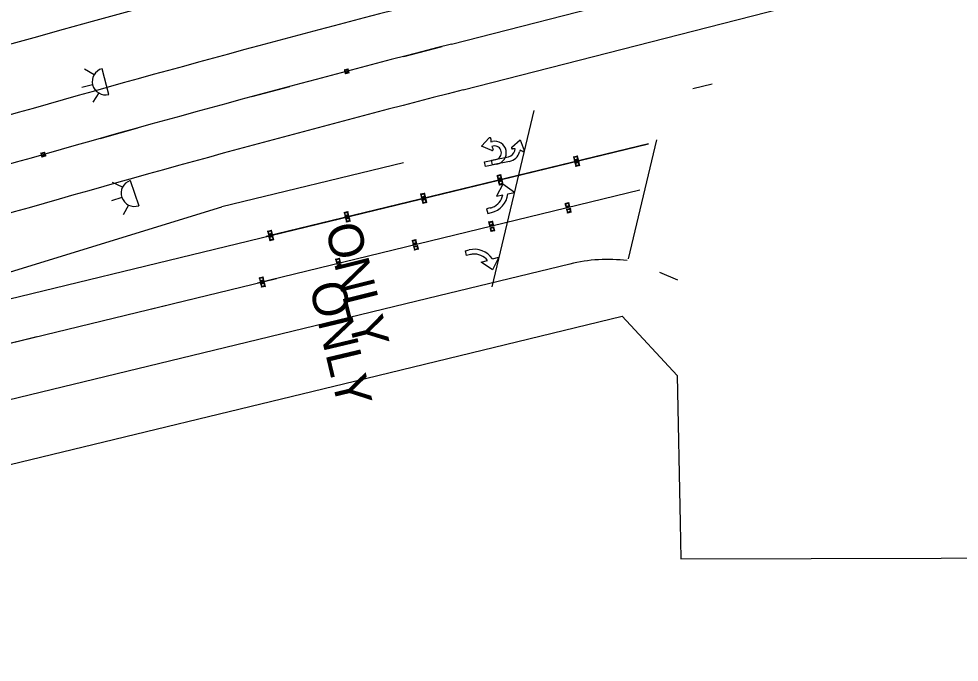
# Model space of a CAD drawing. Extents: x 2471014 to 2497726, y 6959577 to 6980268.
# Drawn here: x 2484090.2 to 2484329.2, y 6967524.6 to 6967688.1 of the extents above; entities that cross this region are included whole.
import ezdxf

# ---------------------------------------------------------------- set-up
doc = ezdxf.new("R2010")
doc.units = 0
for name, color, linetype in [('1', 7, 'Continuous'), ('13', 7, 'Continuous'), ('18', 7, 'Continuous'), ('23', 7, 'Continuous'), ('25', 7, 'Continuous'), ('5', 7, 'Continuous'), ('59', 7, 'Continuous'), ('C-ANNO-NOTE', 7, 'Continuous'), ('Level 30', 7, 'Continuous'), ('p_structure fence', 7, 'Continuous'), ('p_structure wall', 7, 'Continuous'), ('PMK_Del_D-SY_SZ_TYC_CTB', 7, 'Continuous'), ('V7_25', 7, 'Continuous'), ('V7_50', 7, 'Continuous')]:
    doc.layers.add(name, color=color, linetype=linetype)

msp = doc.modelspace()

# ---------------------------------------------------------------- linework, layer by layer
at = {"layer": '1'}
for p, q in [((2484188.08, 6967678.56), (2484197.76, 6967681.06)), ((2484149.41, 6967668.32), (2484159.07, 6967670.92)), ((2484110.85, 6967657.69), (2484120.48, 6967660.38)), ((2484123.99, 6967614.41), (2484133.71, 6967616.76)), ((2484085.12, 6967604.97), (2484094.83, 6967607.33))]:
    msp.add_line(p, q, dxfattribs=at)
at = {"layer": '13'}
for p in [(2484187.94, 6967651.54), (2483808.16, 6967537.76)]:
    msp.add_line(p, (2484141.84, 6967640.35), dxfattribs=at)
msp.add_arc((2485198.7, 6963785.6), 4034, 104.37494, 107.97931, dxfattribs=at)
at = {"layer": '18'}
for p, q in [((2484203.15, 6967670.06), (2484874.76, 6967842.18)), ((2484230.25, 6967625.79), (2484194.15, 6967617.03)), ((2484194.15, 6967617.03), (2484139.68, 6967603.81)), ((2484139.68, 6967603.81), (2483811.46, 6967524.15))]:
    msp.add_line(p, q, dxfattribs=at)
for centre, radius, start, end in [((2486670.96, 6958435.62), 9600, 104.374936, 107.318975), ((2485198.7, 6963785.6), 4010, 104.37494, 107.97931), ((2484239.92, 6967585.95), 41, 83.1069, 103.6414)]:
    msp.add_arc(centre, radius, start, end, dxfattribs=at)
at = {"layer": '23'}
for p, q in [((2484172.95, 6967675.12), (2484173.93, 6967675.38)), ((2484173.15, 6967675.01), (2484172.95, 6967675.12)), ((2484172.95, 6967675.12), (2484173.02, 6967674.86)), ((2484173.02, 6967674.86), (2484173.21, 6967674.14)), ((2484173.32, 6967674.35), (2484173.15, 6967675.01)), ((2484174.19, 6967674.4), (2484173.21, 6967674.14)), ((2484173.21, 6967674.14), (2484173.32, 6967674.35)), ((2484173.93, 6967675.38), (2484173.81, 6967675.18)), ((2484173.81, 6967675.18), (2484173.84, 6967675.04)), ((2484173.84, 6967675.04), (2484173.98, 6967674.52)), ((2484174.19, 6967674.4), (2484173.93, 6967675.38)), ((2484173.98, 6967674.52), (2484174.19, 6967674.4)), ((2484095.79, 6967653.95), (2484096.77, 6967654.23)), ((2484096, 6967653.84), (2484095.79, 6967653.95)), ((2484095.79, 6967653.95), (2484095.87, 6967653.69)), ((2484095.87, 6967653.69), (2484096.07, 6967652.97)), ((2484096.18, 6967653.19), (2484096, 6967653.84)), ((2484097.05, 6967653.25), (2484096.07, 6967652.97)), ((2484096.07, 6967652.97), (2484096.18, 6967653.19)), ((2484096.77, 6967654.23), (2484096.65, 6967654.03)), ((2484096.65, 6967654.03), (2484096.69, 6967653.89)), ((2484096.69, 6967653.89), (2484096.83, 6967653.37)), ((2484097.05, 6967653.25), (2484096.77, 6967654.23)), ((2484096.83, 6967653.37), (2484097.05, 6967653.25)), ((2484231.18, 6967653.02), (2484232.17, 6967653.26)), ((2484231.38, 6967652.91), (2484231.18, 6967653.02)), ((2484231.18, 6967653.02), (2484231.24, 6967652.76)), ((2484231.24, 6967652.76), (2484231.42, 6967652.04)), ((2484231.54, 6967652.25), (2484231.38, 6967652.91)), ((2484232.41, 6967652.28), (2484231.42, 6967652.04)), ((2484231.42, 6967652.04), (2484231.54, 6967652.25)), ((2484232.17, 6967653.26), (2484232.04, 6967653.07)), ((2484232.04, 6967653.07), (2484232.07, 6967652.93)), ((2484232.07, 6967652.93), (2484232.2, 6967652.41)), ((2484232.41, 6967652.28), (2484232.17, 6967653.26)), ((2484232.2, 6967652.41), (2484232.41, 6967652.28)), ((2484231.53, 6967651.57), (2484232.52, 6967651.81)), ((2484231.74, 6967651.45), (2484231.53, 6967651.57)), ((2484231.53, 6967651.57), (2484231.6, 6967651.3)), ((2484231.6, 6967651.3), (2484231.77, 6967650.58)), ((2484231.89, 6967650.79), (2484231.74, 6967651.45)), ((2484232.76, 6967650.82), (2484231.77, 6967650.58)), ((2484231.77, 6967650.58), (2484231.89, 6967650.79)), ((2484232.52, 6967651.81), (2484232.39, 6967651.61)), ((2484232.39, 6967651.61), (2484232.43, 6967651.47)), ((2484232.43, 6967651.47), (2484232.55, 6967650.95)), ((2484232.76, 6967650.82), (2484232.52, 6967651.81)), ((2484232.55, 6967650.95), (2484232.76, 6967650.82)), ((2484211.75, 6967648.31), (2484212.73, 6967648.55)), ((2484211.95, 6967648.19), (2484211.75, 6967648.31)), ((2484211.75, 6967648.31), (2484211.81, 6967648.05)), ((2484211.81, 6967648.05), (2484211.98, 6967647.32)), ((2484212.11, 6967647.53), (2484211.95, 6967648.19)), ((2484212.97, 6967647.56), (2484211.98, 6967647.32)), ((2484211.98, 6967647.32), (2484212.11, 6967647.53)), ((2484212.73, 6967648.55), (2484212.6, 6967648.35)), ((2484212.6, 6967648.35), (2484212.64, 6967648.21)), ((2484212.64, 6967648.21), (2484212.76, 6967647.69)), ((2484212.97, 6967647.56), (2484212.73, 6967648.55)), ((2484212.76, 6967647.69), (2484212.97, 6967647.56)), ((2484212.1, 6967646.85), (2484213.09, 6967647.09)), ((2484212.3, 6967646.73), (2484212.1, 6967646.85)), ((2484212.1, 6967646.85), (2484212.16, 6967646.59)), ((2484212.16, 6967646.59), (2484212.34, 6967645.86)), ((2484212.46, 6967646.08), (2484212.3, 6967646.73)), ((2484213.32, 6967646.1), (2484212.34, 6967645.86)), ((2484212.34, 6967645.86), (2484212.46, 6967646.08)), ((2484213.09, 6967647.09), (2484212.96, 6967646.89)), ((2484212.96, 6967646.89), (2484212.99, 6967646.76)), ((2484212.99, 6967646.76), (2484213.12, 6967646.24)), ((2484213.32, 6967646.1), (2484213.09, 6967647.09)), ((2484213.12, 6967646.24), (2484213.32, 6967646.1)), ((2484192.31, 6967643.59), (2484193.3, 6967643.83)), ((2484192.51, 6967643.47), (2484192.31, 6967643.59)), ((2484192.31, 6967643.59), (2484192.37, 6967643.33)), ((2484192.37, 6967643.33), (2484192.55, 6967642.6)), ((2484192.67, 6967642.82), (2484192.51, 6967643.47)), ((2484193.53, 6967642.84), (2484192.55, 6967642.6)), ((2484192.55, 6967642.6), (2484192.67, 6967642.82)), ((2484193.3, 6967643.83), (2484193.17, 6967643.63)), ((2484193.17, 6967643.63), (2484193.2, 6967643.5)), ((2484193.2, 6967643.5), (2484193.33, 6967642.98)), ((2484193.53, 6967642.84), (2484193.3, 6967643.83)), ((2484193.33, 6967642.98), (2484193.53, 6967642.84)), ((2484192.66, 6967642.13), (2484193.65, 6967642.37)), ((2484192.86, 6967642.02), (2484192.66, 6967642.13)), ((2484192.66, 6967642.13), (2484192.73, 6967641.87)), ((2484192.73, 6967641.87), (2484192.9, 6967641.15)), ((2484193.02, 6967641.36), (2484192.86, 6967642.02)), ((2484193.89, 6967641.39), (2484192.9, 6967641.15)), ((2484192.9, 6967641.15), (2484193.02, 6967641.36)), ((2484193.65, 6967642.37), (2484193.52, 6967642.18)), ((2484193.52, 6967642.18), (2484193.56, 6967642.04)), ((2484193.56, 6967642.04), (2484193.68, 6967641.52)), ((2484193.89, 6967641.39), (2484193.65, 6967642.37)), ((2484193.68, 6967641.52), (2484193.89, 6967641.39)), ((2484229.04, 6967641.18), (2484230.03, 6967641.42)), ((2484229.24, 6967641.07), (2484229.04, 6967641.18)), ((2484229.04, 6967641.18), (2484229.1, 6967640.92)), ((2484229.1, 6967640.92), (2484229.28, 6967640.2)), ((2484229.4, 6967640.41), (2484229.24, 6967641.07)), ((2484230.26, 6967640.44), (2484229.28, 6967640.2)), ((2484229.28, 6967640.2), (2484229.4, 6967640.41)), ((2484230.03, 6967641.42), (2484229.9, 6967641.23)), ((2484229.9, 6967641.23), (2484229.93, 6967641.09)), ((2484229.93, 6967641.09), (2484230.06, 6967640.57)), ((2484230.26, 6967640.44), (2484230.03, 6967641.42)), ((2484230.06, 6967640.57), (2484230.26, 6967640.44)), ((2484172.87, 6967638.87), (2484173.86, 6967639.11)), ((2484173.07, 6967638.76), (2484172.87, 6967638.87)), ((2484172.87, 6967638.87), (2484172.94, 6967638.61)), ((2484172.94, 6967638.61), (2484173.11, 6967637.89)), ((2484173.23, 6967638.1), (2484173.07, 6967638.76)), ((2484174.1, 6967638.13), (2484173.11, 6967637.89)), ((2484173.11, 6967637.89), (2484173.23, 6967638.1)), ((2484173.86, 6967639.11), (2484173.73, 6967638.92)), ((2484173.73, 6967638.92), (2484173.77, 6967638.78)), ((2484173.77, 6967638.78), (2484173.89, 6967638.26)), ((2484174.1, 6967638.13), (2484173.86, 6967639.11)), ((2484173.89, 6967638.26), (2484174.1, 6967638.13)), ((2484229.39, 6967639.73), (2484230.38, 6967639.97)), ((2484229.59, 6967639.61), (2484229.39, 6967639.73)), ((2484229.39, 6967639.73), (2484229.46, 6967639.47)), ((2484229.46, 6967639.47), (2484229.63, 6967638.74)), ((2484229.75, 6967638.95), (2484229.59, 6967639.61)), ((2484230.62, 6967638.98), (2484229.63, 6967638.74)), ((2484229.63, 6967638.74), (2484229.75, 6967638.95)), ((2484230.38, 6967639.97), (2484230.25, 6967639.77)), ((2484230.25, 6967639.77), (2484230.28, 6967639.63)), ((2484230.28, 6967639.63), (2484230.41, 6967639.11)), ((2484230.62, 6967638.98), (2484230.38, 6967639.97)), ((2484230.41, 6967639.11), (2484230.62, 6967638.98)), ((2484173.23, 6967637.42), (2484174.21, 6967637.65)), ((2484173.43, 6967637.3), (2484173.23, 6967637.42)), ((2484173.23, 6967637.42), (2484173.29, 6967637.15)), ((2484173.29, 6967637.15), (2484173.47, 6967636.43)), ((2484173.59, 6967636.64), (2484173.43, 6967637.3)), ((2484174.45, 6967636.67), (2484173.47, 6967636.43)), ((2484173.47, 6967636.43), (2484173.59, 6967636.64)), ((2484174.21, 6967637.65), (2484174.09, 6967637.46)), ((2484174.09, 6967637.46), (2484174.12, 6967637.32)), ((2484174.12, 6967637.32), (2484174.25, 6967636.8)), ((2484174.45, 6967636.67), (2484174.21, 6967637.65)), ((2484174.25, 6967636.8), (2484174.45, 6967636.67)), ((2484209.6, 6967636.47), (2484210.59, 6967636.71)), ((2484209.8, 6967636.35), (2484209.6, 6967636.47)), ((2484209.6, 6967636.47), (2484209.67, 6967636.21)), ((2484209.67, 6967636.21), (2484209.84, 6967635.48)), ((2484209.96, 6967635.69), (2484209.8, 6967636.35)), ((2484210.83, 6967635.72), (2484209.84, 6967635.48)), ((2484209.84, 6967635.48), (2484209.96, 6967635.69)), ((2484210.59, 6967636.71), (2484210.46, 6967636.51)), ((2484210.46, 6967636.51), (2484210.49, 6967636.37)), ((2484210.49, 6967636.37), (2484210.62, 6967635.85)), ((2484210.83, 6967635.72), (2484210.59, 6967636.71)), ((2484210.62, 6967635.85), (2484210.83, 6967635.72)), ((2484153.44, 6967634.16), (2484154.42, 6967634.4)), ((2484153.64, 6967634.04), (2484153.44, 6967634.16)), ((2484153.44, 6967634.16), (2484153.5, 6967633.89)), ((2484153.5, 6967633.89), (2484153.68, 6967633.17)), ((2484153.8, 6967633.38), (2484153.64, 6967634.04)), ((2484154.66, 6967633.41), (2484153.68, 6967633.17)), ((2484153.68, 6967633.17), (2484153.8, 6967633.38)), ((2484154.42, 6967634.4), (2484154.3, 6967634.2)), ((2484154.3, 6967634.2), (2484154.33, 6967634.06)), ((2484154.33, 6967634.06), (2484154.46, 6967633.54)), ((2484154.66, 6967633.41), (2484154.42, 6967634.4)), ((2484154.46, 6967633.54), (2484154.66, 6967633.41)), ((2484209.96, 6967635.01), (2484210.94, 6967635.25)), ((2484210.16, 6967634.89), (2484209.96, 6967635.01)), ((2484209.96, 6967635.01), (2484210.02, 6967634.75)), ((2484210.02, 6967634.75), (2484210.2, 6967634.02)), ((2484210.32, 6967634.24), (2484210.16, 6967634.89)), ((2484211.18, 6967634.26), (2484210.2, 6967634.02)), ((2484210.2, 6967634.02), (2484210.32, 6967634.24)), ((2484210.94, 6967635.25), (2484210.82, 6967635.05)), ((2484210.82, 6967635.05), (2484210.85, 6967634.92)), ((2484210.85, 6967634.92), (2484210.98, 6967634.4)), ((2484211.18, 6967634.26), (2484210.94, 6967635.25)), ((2484210.98, 6967634.4), (2484211.18, 6967634.26)), ((2484153.79, 6967632.7), (2484154.78, 6967632.94)), ((2484153.99, 6967632.58), (2484153.79, 6967632.7)), ((2484153.79, 6967632.7), (2484153.85, 6967632.44)), ((2484153.85, 6967632.44), (2484154.03, 6967631.71)), ((2484154.15, 6967631.92), (2484153.99, 6967632.58)), ((2484155.02, 6967631.95), (2484154.03, 6967631.71)), ((2484154.03, 6967631.71), (2484154.15, 6967631.92)), ((2484154.78, 6967632.94), (2484154.65, 6967632.74)), ((2484154.65, 6967632.74), (2484154.68, 6967632.61)), ((2484154.68, 6967632.61), (2484154.81, 6967632.08)), ((2484155.02, 6967631.95), (2484154.78, 6967632.94)), ((2484154.81, 6967632.08), (2484155.02, 6967631.95)), ((2484190.17, 6967631.75), (2484191.15, 6967631.99)), ((2484190.37, 6967631.64), (2484190.17, 6967631.75)), ((2484190.17, 6967631.75), (2484190.23, 6967631.49)), ((2484190.23, 6967631.49), (2484190.41, 6967630.77)), ((2484190.53, 6967630.98), (2484190.37, 6967631.64)), ((2484191.39, 6967631), (2484190.41, 6967630.77)), ((2484190.41, 6967630.77), (2484190.53, 6967630.98)), ((2484191.15, 6967631.99), (2484191.03, 6967631.8)), ((2484191.03, 6967631.8), (2484191.06, 6967631.66)), ((2484191.06, 6967631.66), (2484191.19, 6967631.14)), ((2484191.39, 6967631), (2484191.15, 6967631.99)), ((2484191.19, 6967631.14), (2484191.39, 6967631)), ((2484190.52, 6967630.29), (2484191.51, 6967630.53)), ((2484190.72, 6967630.18), (2484190.52, 6967630.29)), ((2484190.52, 6967630.29), (2484190.58, 6967630.03)), ((2484190.58, 6967630.03), (2484190.76, 6967629.31)), ((2484190.88, 6967629.52), (2484190.72, 6967630.18)), ((2484191.75, 6967629.55), (2484190.76, 6967629.31)), ((2484190.76, 6967629.31), (2484190.88, 6967629.52)), ((2484191.51, 6967630.53), (2484191.38, 6967630.34)), ((2484191.38, 6967630.34), (2484191.41, 6967630.2)), ((2484191.41, 6967630.2), (2484191.54, 6967629.68)), ((2484191.75, 6967629.55), (2484191.51, 6967630.53)), ((2484191.54, 6967629.68), (2484191.75, 6967629.55)), ((2484170.73, 6967627.03), (2484171.72, 6967627.27)), ((2484170.93, 6967626.92), (2484170.73, 6967627.03)), ((2484170.73, 6967627.03), (2484170.79, 6967626.77)), ((2484170.79, 6967626.77), (2484170.97, 6967626.05)), ((2484171.09, 6967626.26), (2484170.93, 6967626.92)), ((2484171.96, 6967626.29), (2484170.97, 6967626.05)), ((2484170.97, 6967626.05), (2484171.09, 6967626.26)), ((2484171.72, 6967627.27), (2484171.59, 6967627.08)), ((2484171.59, 6967627.08), (2484171.62, 6967626.94)), ((2484171.62, 6967626.94), (2484171.75, 6967626.42)), ((2484171.96, 6967626.29), (2484171.72, 6967627.27)), ((2484171.75, 6967626.42), (2484171.96, 6967626.29)), ((2484171.08, 6967625.58), (2484172.07, 6967625.82)), ((2484171.29, 6967625.46), (2484171.08, 6967625.58)), ((2484171.08, 6967625.58), (2484171.15, 6967625.31)), ((2484171.15, 6967625.31), (2484171.32, 6967624.59)), ((2484171.45, 6967624.8), (2484171.29, 6967625.46)), ((2484172.31, 6967624.83), (2484171.32, 6967624.59)), ((2484171.32, 6967624.59), (2484171.45, 6967624.8)), ((2484172.07, 6967625.82), (2484171.94, 6967625.62)), ((2484171.94, 6967625.62), (2484171.98, 6967625.48)), ((2484171.98, 6967625.48), (2484172.1, 6967624.96)), ((2484172.31, 6967624.83), (2484172.07, 6967625.82)), ((2484172.1, 6967624.96), (2484172.31, 6967624.83)), ((2484151.3, 6967622.32), (2484152.28, 6967622.56)), ((2484151.5, 6967622.2), (2484151.3, 6967622.32)), ((2484151.3, 6967622.32), (2484151.36, 6967622.06)), ((2484151.36, 6967622.06), (2484151.53, 6967621.33)), ((2484151.66, 6967621.54), (2484151.5, 6967622.2)), ((2484152.52, 6967621.57), (2484151.53, 6967621.33)), ((2484151.53, 6967621.33), (2484151.66, 6967621.54)), ((2484152.28, 6967622.56), (2484152.15, 6967622.36)), ((2484152.15, 6967622.36), (2484152.19, 6967622.22)), ((2484152.19, 6967622.22), (2484152.31, 6967621.7)), ((2484152.52, 6967621.57), (2484152.28, 6967622.56)), ((2484152.31, 6967621.7), (2484152.52, 6967621.57)), ((2484151.65, 6967620.86), (2484152.64, 6967621.1)), ((2484151.85, 6967620.74), (2484151.65, 6967620.86)), ((2484151.65, 6967620.86), (2484151.71, 6967620.6)), ((2484151.71, 6967620.6), (2484151.89, 6967619.87)), ((2484152.01, 6967620.09), (2484151.85, 6967620.74)), ((2484152.87, 6967620.11), (2484151.89, 6967619.87)), ((2484151.89, 6967619.87), (2484152.01, 6967620.09)), ((2484152.64, 6967621.1), (2484152.51, 6967620.9)), ((2484152.51, 6967620.9), (2484152.54, 6967620.77)), ((2484152.54, 6967620.77), (2484152.67, 6967620.25)), ((2484152.87, 6967620.11), (2484152.64, 6967621.1)), ((2484152.67, 6967620.25), (2484152.87, 6967620.11))]:
    msp.add_line(p, q, dxfattribs=at)
for points in [[(2484173.15, 6967675.01), (2484173.81, 6967675.18), (2484173.98, 6967674.52), (2484173.32, 6967674.35)], [(2484096, 6967653.84), (2484096.65, 6967654.03), (2484096.83, 6967653.37), (2484096.18, 6967653.19)], [(2484231.38, 6967652.91), (2484232.04, 6967653.07), (2484232.2, 6967652.41), (2484231.54, 6967652.25)], [(2484231.74, 6967651.45), (2484232.39, 6967651.61), (2484232.55, 6967650.95), (2484231.89, 6967650.79)], [(2484211.95, 6967648.19), (2484212.6, 6967648.35), (2484212.76, 6967647.69), (2484212.11, 6967647.53)], [(2484212.3, 6967646.73), (2484212.96, 6967646.89), (2484213.12, 6967646.24), (2484212.46, 6967646.08)], [(2484192.51, 6967643.47), (2484193.17, 6967643.63), (2484193.33, 6967642.98), (2484192.67, 6967642.82)], [(2484192.86, 6967642.02), (2484193.52, 6967642.18), (2484193.68, 6967641.52), (2484193.02, 6967641.36)], [(2484229.24, 6967641.07), (2484229.9, 6967641.23), (2484230.06, 6967640.57), (2484229.4, 6967640.41)], [(2484173.07, 6967638.76), (2484173.73, 6967638.92), (2484173.89, 6967638.26), (2484173.23, 6967638.1)], [(2484229.59, 6967639.61), (2484230.25, 6967639.77), (2484230.41, 6967639.11), (2484229.75, 6967638.95)], [(2484173.43, 6967637.3), (2484174.09, 6967637.46), (2484174.25, 6967636.8), (2484173.59, 6967636.64)], [(2484209.8, 6967636.35), (2484210.46, 6967636.51), (2484210.62, 6967635.85), (2484209.96, 6967635.69)], [(2484153.64, 6967634.04), (2484154.3, 6967634.2), (2484154.46, 6967633.54), (2484153.8, 6967633.38)], [(2484210.16, 6967634.89), (2484210.82, 6967635.05), (2484210.98, 6967634.4), (2484210.32, 6967634.24)], [(2484153.99, 6967632.58), (2484154.65, 6967632.74), (2484154.81, 6967632.08), (2484154.15, 6967631.92)], [(2484190.37, 6967631.64), (2484191.03, 6967631.8), (2484191.19, 6967631.14), (2484190.53, 6967630.98)], [(2484190.72, 6967630.18), (2484191.38, 6967630.34), (2484191.54, 6967629.68), (2484190.88, 6967629.52)], [(2484170.93, 6967626.92), (2484171.59, 6967627.08), (2484171.75, 6967626.42), (2484171.09, 6967626.26)], [(2484171.29, 6967625.46), (2484171.94, 6967625.62), (2484172.1, 6967624.96), (2484171.45, 6967624.8)], [(2484151.5, 6967622.2), (2484152.15, 6967622.36), (2484152.31, 6967621.7), (2484151.66, 6967621.54)], [(2484151.85, 6967620.74), (2484152.51, 6967620.9), (2484152.67, 6967620.25), (2484152.01, 6967620.09)]]:
    msp.add_lwpolyline(points, close=True, dxfattribs=at)
at = {"layer": '25'}
for p, q in [((2484250.22, 6967656.36), (2484153.04, 6967632.78)), ((2484248.07, 6967644.52), (2484150.9, 6967620.94))]:
    msp.add_line(p, q, dxfattribs=at)
at = {"layer": '5'}
msp.add_arc((2479474.04, 6969335.88), 8460, 6.37617, 6.37617, dxfattribs=at)
at = {"layer": '59'}
for radius in [8476, 8488]:
    msp.add_arc((2482064.37, 6975940.32), radius, 282.408529, 284.180971, dxfattribs=at)
at = {"layer": 'C-ANNO-NOTE'}
for p, q in [((2484200.17, 6967681.68), (2484871.73, 6967853.8)), ((2484261.53, 6967670.42), (2484266.39, 6967671.6)), ((2484221.13, 6967664.79), (2484210.44, 6967619.95)), ((2484252.25, 6967657.37), (2484245.05, 6967627.13)), ((2484004.78, 6967596.79), (2484250.22, 6967656.36)), ((2484253.01, 6967623.74), (2484257.63, 6967621.81)), ((2484007.37, 6967586.1), (2484155.66, 6967622.09))]:
    msp.add_line(p, q, dxfattribs=at)
msp.add_arc((2485198.7, 6963785.6), 4022, 104.37494, 107.97931, dxfattribs=at)
at = {"layer": 'Level 30'}
for p, q in [((2484116.57, 6967645.29), (2484114.03, 6967646.5)), ((2484118.51, 6967647), (2484120.68, 6967640.61)), ((2484116.4, 6967642.71), (2484113.74, 6967641.81)), ((2484118.1, 6967640.77), (2484116.77, 6967638.3))]:
    msp.add_line(p, q, dxfattribs=at)
msp.add_arc((2484119.6, 6967643.8), 3.37, 108.7842, 288.7842, dxfattribs=at)
at = {"layer": 'p_structure wall'}
for p, q in [((2484207.78, 6967655.77), (2484209.77, 6967657.82)), ((2484210.2, 6967657.64), (2484210.17, 6967656.88)), ((2484210.17, 6967656.88), (2484210.56, 6967656.95)), ((2484215.47, 6967655.48), (2484217.63, 6967657.36)), ((2484217.63, 6967657.36), (2484218.61, 6967654.67)), ((2484210.41, 6967654.64), (2484207.78, 6967655.77)), ((2484210.8, 6967655.75), (2484210.41, 6967655.67)), ((2484210.41, 6967655.67), (2484210.73, 6967654.97)), ((2484216.39, 6967655.04), (2484215.63, 6967655.05)), ((2484216.28, 6967654.58), (2484216.39, 6967655.04)), ((2484217.59, 6967654.73), (2484217.47, 6967654.28)), ((2484218.26, 6967654.37), (2484217.59, 6967654.73)), ((2484208.58, 6967651.78), (2484211.48, 6967652.36)), ((2484210.31, 6967652.18), (2484214.66, 6967653.05)), ((2484210.56, 6967650.97), (2484210.31, 6967652.18)), ((2484208.83, 6967650.57), (2484208.58, 6967651.78)), ((2484211.73, 6967651.16), (2484208.83, 6967650.57)), ((2484214.91, 6967651.85), (2484210.56, 6967650.97)), ((2484213.23, 6967646.07), (2484211.6, 6967642.99)), ((2484216.17, 6967643.99), (2484213.23, 6967646.07)), ((2484211.6, 6967642.99), (2484213.23, 6967643.38)), ((2484214.5, 6967643.59), (2484216.17, 6967643.99)), ((2484210.04, 6967640.04), (2484209.08, 6967639.81)), ((2484209.08, 6967639.81), (2484209.37, 6967638.61)), ((2484209.37, 6967638.61), (2484210.33, 6967638.84)), ((2484203.72, 6967629.14), (2484204.68, 6967629.38)), ((2484204.02, 6967627.95), (2484203.72, 6967629.14)), ((2484204.98, 6967628.19), (2484204.02, 6967627.95)), ((2484207.72, 6967626.29), (2484209.34, 6967626.69)), ((2484210.59, 6967624.3), (2484207.72, 6967626.29)), ((2484210.57, 6967627.09), (2484212.24, 6967627.5)), ((2484212.24, 6967627.5), (2484210.59, 6967624.3))]:
    msp.add_line(p, q, dxfattribs=at)
for centre, radius, start, end in [((2484209.95, 6967657.65), 0.246, 357.9054, 135.8914), ((2484211.14, 6967654.05), 2.96, 281.3726, 101.3725), ((2484210.51, 6967654.87), 0.246, 246.8533, 24.8393), ((2484211.14, 6967654.05), 1.73, 281.3726, 101.3725), ((2484214.25, 6967655.11), 2.09, 281.3726, 345.5084), ((2484215.64, 6967655.3), 0.246, 130.9875, 269.0044), ((2484218.38, 6967654.59), 0.246, 242.0846, 20.054), ((2484214.25, 6967655.11), 3.32, 281.3726, 345.5084), ((2484209.04, 6967644.18), 5.49, 283.5379, 353.8273), ((2484209.04, 6967644.18), 4.26, 291.4091, 349.1517), ((2484209.04, 6967644.18), 4.26, 283.5789, 289.1617), ((2484209.04, 6967644.18), 4.26, 289.1617, 291.4091), ((2484206, 6967624.05), 5.49, 33.616, 103.9054), ((2484206, 6967624.05), 4.26, 96.0342, 98.2816), ((2484206, 6967624.05), 4.26, 38.2916, 96.0342), ((2484206, 6967624.05), 4.26, 98.2816, 103.8643)]:
    msp.add_arc(centre, radius, start, end, dxfattribs=at)
at = {"layer": 'PMK_Del_D-SY_SZ_TYC_CTB'}
for p, q in [((2484109.32, 6967673.87), (2484106.88, 6967675.27)), ((2484113.07, 6967668.88), (2484111.39, 6967675.42)), ((2484108.96, 6967671.31), (2484106.23, 6967670.61)), ((2484110.51, 6967669.25), (2484108.99, 6967666.88))]:
    msp.add_line(p, q, dxfattribs=at)
msp.add_arc((2484112.23, 6967672.15), 3.37, 104.3978, 284.3978, dxfattribs=at)
at = {"layer": 'V7_25'}
for radius in [8452, 8464]:
    msp.add_arc((2482064.37, 6975940.32), radius, 282.408529, 284.180971, dxfattribs=at)
at = {"layer": 'V7_50'}
msp.add_lwpolyline([(2483270.89, 6967411.98), (2483478.09, 6967446.69), (2483743.04, 6967491.08), (2483822.84, 6967510.45), (2484088.03, 6967574.81), (2484175.49, 6967596.03), (2484243.52, 6967612.54), (2484257.54, 6967597.42), (2484258.29, 6967560.02), (2484258.47, 6967550.85), (2484357.78, 6967551.14), (2484359.02, 6967215.32), (2484363.23, 6967216.39), (2484385.19, 6967216.41), (2484383.19, 6967316.75), (2484382.18, 6967366.74), (2484392.7, 6967390.4), (2484388.08, 6967523.27), (2484376.95, 6967628), (2484375.63, 6967693.89), (2484447.6, 6967710.17), (2484746.88, 6967763.8)], dxfattribs=at)
msp.add_ellipse((2484308.07, 6967658.79), major_axis=(23.18, -533), ratio=0.5, dxfattribs=at)

# ---------------------------------------------------------------- texts
at = {"layer": 'p_structure fence'}
for rotation, p in [(284.0383, (2484168, 6967635.13)), (283.4049, (2484163.97, 6967620.32))]:
    msp.add_text('ONLY', height=8.898, rotation=rotation, dxfattribs=at).set_placement(p)

doc.saveas('drawing.dxf')
